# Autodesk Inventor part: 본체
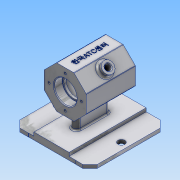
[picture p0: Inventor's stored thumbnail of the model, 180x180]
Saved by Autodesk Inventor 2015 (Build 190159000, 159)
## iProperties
Created: 2018-06
Part Number: 본체
Material: 알루미늄 6061
Document SubType Name: Modeling
Designer: SCD-A04
Density: 2.7 g/cm^3
Appearance: 알루미늄 - 평지
Mass: 551.998 g
Surface Area: 602.169 cm^2
Volume: 204.444 cm^3
Author: SCD-A04
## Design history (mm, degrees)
sketch "스케치2"
  geometry: L1 (-55, 55.234)-(55, 55.234); L2 (55, 55.234)-(55, -54.766); L3 (55, -54.766)-(-55, -54.766); L4 (-55, -54.766)-(-55, 55.234); L5 (-55, 55.234)-(55, -54.766); L6 (55, 55.234)-(-55, -54.766); 2 further points
  constraints: 12 end point, 2 midpoint, 2 parallel, 1 horizontal, 1 perpendicular
  dimensions: "d0" = 110 distance of L2.end L3.end; "d1" = 110 distance of L1.end L2.end
extrude "돌출1" new body sketch "스케치2" distance "d2" = 5; taper "d3" = 0 deg
sketch "스케치3"
  geometry: L1 (-25, 55.234)-(25, 55.234); L2 (25, 55.234)-(25, -55.234); L3 (25, -55.234)-(-25, -55.234); L4 (-25, -55.234)-(-25, 55.234); L5 (-25, 55.234)-(25, -55.234); L6 (25, 55.234)-(-25, -55.234); L7 (55, 55.234)-(-55, 55.234) reference; 2 further points
  constraints: 12 end point, 4 midpoint, 1 horizontal, 1 vertical
  dimensions: "d4" = 50 distance of L2.end L3.end; "d77" = 50 distance of L1.start L1.end
extrude "돌출2" join sketch "스케치3" distance "d6" = 5; taper "d7" = 0 deg
sketch "스케치13"
  geometry: L1 (-32.4, -54.601)-(34.142, -54.601); L2 (34.142, -54.601)-(34.142, -64.651); L3 (34.142, -64.651)-(-32.4, -64.651); L4 (-32.4, -64.651)-(-32.4, -54.601); 1 further point
  constraints: 8 end point, 2 parallel, 1 horizontal, 1 perpendicular
extrude "돌출7" cut sketch "스케치13" distance "d78" = 12; taper "d79" = 0 deg
sketch "스케치4"
  geometry: L1 (-55, 55.234)-(-55, -54.766) reference; 2 further points
  constraints: 1 horizontal alignment
  dimensions: "d8" = 10 distance from line of point (-45, 0) L1
hole "구멍1" sketch "스케치4" at (-45, 0) diameter "d9" = 10; stored, may be unused: countersink angle "d13" = 90 deg, drill point angle "d15" = 118 deg; dims "d10" = 6, "d11" = 4, "d12" = 2, "d14" = 8
sketch "스케치5"
  geometry: L1 (0, 19)-(0, -19); L2 (-5, 19)-(-5, -19); L3 (5, -19)-(5, 19); A1 r 5 centre (0, 19) between (5, 19) and (-5, 19); A2 r 5 centre (0, -19) between (-5, -19) and (5, -19); 1 further point
  constraints: 8 end point, 4 point on circle, 4 tangent, 2 centre point, 1 midpoint, 1 parallel, 1 vertical
  dimensions: "d16" = 10 diameter of A2; "d17" = 38 distance of L1.start L1.end
extrude "돌출3" join sketch "스케치5" distance "d18" = 52; taper "d19" = 0 deg
chamfer "모따기1" distance "d20" = 10; stored, may be unused: second distance "d21" = 2, angle "d22" = 45 deg
sketch "스케치6"
  geometry: L1 (55, 0)-(50, 0) reference; L2 (50, 0)-(50, 5) reference; L3 (50, 5)-(55, 5) reference; L4 (55, 5)-(55, 0) reference; L5 (-50, 0)-(-55, 0) reference; L6 (-55, 0)-(-55, 5) reference; L7 (-55, 5)-(-50, 5) reference; L8 (-50, 5)-(-50, 0) reference; L9 (25, 10)-(25, 5) reference; L10 (25, 5)-(40, 5) reference; L11 (40, 5)-(40, 0) reference; L12 (40, 0)-(-40, 0) reference; L13 (-40, 0)-(-40, 5) reference; L14 (-40, 5)-(-25, 5) reference; L15 (-25, 5)-(-25, 10) reference; L16 (-25, 10)-(-5, 10) reference; L17 (-5, 10)-(-5, 62) reference; L18 (-5, 62)-(5, 62) reference; L19 (5, 62)-(5, 10) reference; L20 (5, 10)-(25, 10) reference; L21 (-30, 49.574)-(-30, 74.426); L22 (-30, 74.426)-(-12.426, 92); L23 (-12.426, 92)-(12.426, 92); L24 (12.426, 92)-(30, 74.426); L25 (30, 74.426)-(30, 49.574); L26 (30, 49.574)-(12.426, 32); L27 (12.426, 32)-(-12.426, 32); L28 (-12.426, 32)-(-30, 49.574); 2 further points
  constraints: 16 end point, 1 midpoint, 1 parallel, 1 vertical alignment, 17 other
  dimensions: "d23" = 30 distance from line of L28 point (0, 62)
extrude "돌출4" join sketch "스케치6" stored distance "d24" = 70; taper "d25" = 0 deg
sketch "스케치7"
  geometry: L1 (-24.853, 70)-(0, 70) reference; L2 (0, 0)-(-24.853, 0) reference; C1 r 8 at (-12.426, 35); 3 further points
  constraints: 1 centre point, 1 coincident, 1 midpoint, 1 vertical alignment
  dimensions: "d26" = 35 distance from line of L2 point (-12.426, 35); "d27" = 16 diameter of C1
extrude "돌출5" join sketch "스케치7" distance "d28" = 7; taper "d29" = 0 deg
sketch "스케치8"
  geometry: L1 (45, 0)-(-45, 0) reference; 3 further points
  constraints: 1 midpoint, 1 vertical alignment
  dimensions: "d30" = 62 distance from line of L1 point (0, 62)
hole "구멍2" sketch "스케치8" at (0, 62) diameter "d31" = 28; stored, may be unused: countersink angle "d35" = 90 deg, drill point angle "d37" = 118 deg; dims "d32" = 6, "d33" = 32, "d34" = 12, "d36" = 8
sketch "스케치9"
  geometry: L1 (-45, 0)-(45, 0) reference; C1 r 14 at (0, -62) reference; C2 r 16 at (0, -62); 2 further points
  constraints: 1 centre point, 1 coincident, 1 midpoint, 1 vertical alignment
  dimensions: "d38" = 32 diameter of C2
extrude "돌출6" cut sketch "스케치9" distance "d39" = 12; taper "d40" = 0 deg
sketch "스케치10"
  geometry: L1 (-23, 76)-(-23, 78) reference; L2 (-23, 78)-(-35, 78) reference; L3 (-35, 78)-(-35, 92) reference; L4 (-35, 92)-(35, 92) reference; L5 (35, 92)-(35, 78) reference; L6 (35, 78)-(23, 78) reference; L7 (23, 78)-(23, 76) reference; L8 (23, 76)-(-23, 76) reference; L9 (55.234, 10)-(55.234, 0) reference; L10 (55.234, 0)-(-54.601, 0) reference; L11 (-54.601, 10)-(-24, 10) reference; L12 (-24, 10)-(-24, 32) reference; L13 (-24, 32)-(-35, 32) reference; L14 (-35, 32)-(-35, 46) reference; L15 (-35, 46)-(-23, 46) reference; L16 (-23, 46)-(-23, 48) reference; L17 (-23, 48)-(23, 48) reference; L18 (23, 48)-(23, 46) reference; L19 (23, 46)-(35, 46) reference; L20 (35, 46)-(35, 32) reference; L21 (35, 32)-(24, 32) reference; L22 (24, 32)-(24, 10) reference; L23 (24, 10)-(55.234, 10) reference; L24 (20.317, 87)-(-19.683, 87); L25 (-19.683, 87)-(-19.683, 62); L26 (-19.683, 62)-(20.317, 62); L27 (20.317, 62)-(20.317, 87); L28 (20.317, 87)-(-19.683, 62); L29 (-19.683, 87)-(20.317, 62); L30 (-54.601, 0)-(-54.601, 10) reference; 4 further points
  constraints: 12 end point, 4 midpoint, 2 parallel, 1 horizontal, 1 perpendicular, 1 vertical alignment
  dimensions: "d41" = 62 distance between parallel lines of L10 L26; "d42" = 25 distance of L26.end L24.start; "d43" = 40 distance of L24.start L24.end
revolve "회전1" sketch "스케치10" stored, may be unused: angle "d44" = 90 deg
hole "구멍3" diameter "d47" = 8; stored, may be unused: countersink angle "d51" = 90 deg, drill point angle "d53" = 118 deg; dims "d45" = 10, "d46" = 10, "d48" = 6, "d49" = 32, "d50" = 12, "d52" = 8
sketch "스케치11"
  geometry: L1 (45, 0)-(-45, 0) reference; C1 r 16 at (0, 62) reference; 3 further points
  constraints: 1 midpoint, 1 vertical alignment
  dimensions: "d54" = 23 distance of C1.centre point (0, 85)
hole "구멍4" sketch "스케치11" at (0, 85) diameter "d55" = 3.242; stored, may be unused: countersink angle "d59" = 90 deg, drill point angle "d61" = 118 deg; dims "d56" = 8, "d57" = 32, "d58" = 12, "d60" = 10
fillet "모깎기1" dims "d65" = 1
chamfer "모따기2" distance "d66" = 1; stored, may be unused: second distance "d67" = 2, angle "d68" = 45 deg
fillet "모깎기2" dims "d69" = 0.3
fillet "모깎기3" dims "d70" = 3
fillet "모깎기4" dims "d71" = 2
fillet "모깎기5" dims "d72" = 3
sketch "스케치12"
  geometry: L1 (24.024, 0)-(0, 0) reference; L2 (42.012, 0)-(42.012, 70) reference; 2 further points
  constraints: 1 other
  dimensions: "d73" = 35 distance from line of L1 point (12.012, 35); "d74" = 30 distance from line of L2 point (12.012, 35)
feature "엠보싱1" sketch "스케치12" dims "d0" = 110, "d1" = 110, "d9" = 10, "d11" = 4, "d12" = 2, "d14" = 8, "d75" = 0.5, "d76" = 0
node "솔리드1"
mirror "대칭1"
pattern_circular "원형 패턴1" dims angle "d63" = 360 deg
mirror "대칭2"
node "절단 모서리 투영1"
node "절단 모서리 투영2"
